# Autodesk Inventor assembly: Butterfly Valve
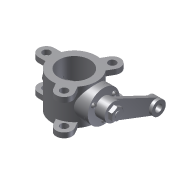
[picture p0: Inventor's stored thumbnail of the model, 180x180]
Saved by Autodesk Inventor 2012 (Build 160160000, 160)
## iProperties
Created: 2011-07
Part Number: Butterfly Valve
Document SubType Name: Assembly
Designer: CadCim
Author: CadCim
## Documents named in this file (8)
- C:\Users\CadCim\Documents\SAILESH\inventor-2011-fact-prt\c13-inv-2011-prt\c13_inv_2012_prt\Exercise\c13_exr01_inv\Butterfly Valve.iam
- C:\Users\CadCim\Documents\SAILESH\inventor-2011-fact-prt\c13-inv-2011-prt\c13_inv_2012_prt\Exercise\c13_exr01_inv\Body.ipt
- C:\Users\CadCim\Documents\SAILESH\inventor-2011-fact-prt\c13-inv-2011-prt\c13_inv_2012_prt\Exercise\c13_exr01_inv\Shaft.ipt
- C:\Users\CadCim\Documents\SAILESH\inventor-2011-fact-prt\c13-inv-2011-prt\c13_inv_2012_prt\Exercise\c13_exr01_inv\Retainer.ipt
- C:\Users\CadCim\Documents\SAILESH\inventor-2011-fact-prt\c13-inv-2011-prt\c13_inv_2012_prt\Exercise\c13_exr01_inv\Arm.ipt
- C:\Users\CadCim\Documents\SAILESH\inventor-2011-fact-prt\c13-inv-2011-prt\c13_inv_2012_prt\Exercise\c13_exr01_inv\Plate.ipt
- C:\Users\CadCim\Documents\SAILESH\inventor-2011-fact-prt\c13-inv-2011-prt\c13_inv_2012_prt\Exercise\c13_exr01_inv\Screw.ipt
- C:\Users\CadCim\Documents\SAILESH\inventor-2011-fact-prt\c13-inv-2011-prt\c13_inv_2012_prt\Exercise\c13_exr01_inv\Nut.ipt
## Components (9 placed, 7 different names)
1. Body:1 — Insert:1, Insert:2, Insert:3, Angle:1
2. Shaft:1 — Insert:1, Mate:1, Angle:1, Insert:5, Insert:6, Insert:10
3. Retainer:1 — Insert:2, Insert:3, Insert:4, Insert:7, Insert:8, Insert:9
4. Arm:1 — Insert:4, Mate:1
5. Plate:1 — Insert:5, Insert:6
6. Screw:1 — Insert:7
7. Screw:2 — Insert:8
8. Screw:3 — Insert:9
9. Nut:1 — Insert:10
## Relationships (12: Insert 10, Mate 1, Angle 1)
- Insert:1: Body:1 ↔ Shaft:1
- Insert:2: Body:1 ↔ Retainer:1
- Insert:3: Body:1 ↔ Retainer:1
- Insert:4: Retainer:1 ↔ Arm:1
- Mate:1: Shaft:1 ↔ Arm:1
- Angle:1: Body:1 ↔ Shaft:1
- Insert:5: Shaft:1 ↔ Plate:1
- Insert:6: Shaft:1 ↔ Plate:1
- Insert:7: Retainer:1 ↔ Screw:1
- Insert:8: Retainer:1 ↔ Screw:2
- Insert:9: Retainer:1 ↔ Screw:3
- Insert:10: Shaft:1 ↔ Nut:1
